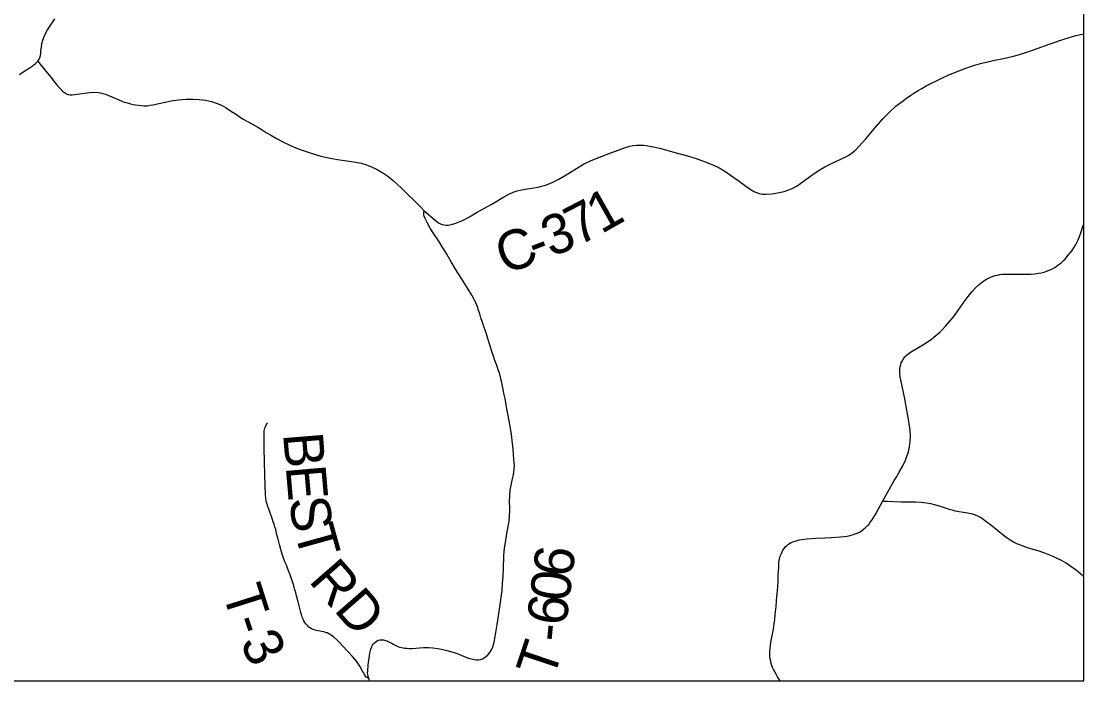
# Model space of a CAD drawing. Extents: x -10.5 to 40.6, y -3.2 to 22.
# Drawn here: x -5.263 to -3.744, y 14.1 to 15.042 of the extents above; entities that cross this region are included whole.
import ezdxf

# ---------------------------------------------------------------- set-up
doc = ezdxf.new("R2010")
doc.units = 0
for name, color, linetype in [('GM_X_County_Road', 7, 'Continuous'), ('GM_X_County_Road_Text', 7, 'Continuous'), ('GM_X_Township_Road', 7, 'Continuous'), ('GM_X_Township_Road_Text', 7, 'Continuous'), ('GM_X_Township_Text', 7, 'Continuous')]:
    doc.layers.add(name, color=color, linetype=linetype)

msp = doc.modelspace()

# ---------------------------------------------------------------- linework, layer by layer
at = {"layer": 'GM_X_County_Road'}
for points in [[(-5.239, 14.9851), (-5.2371, 14.988), (-5.2358, 14.9913), (-5.2349, 14.9959), (-5.2345, 14.9996), (-5.2338, 15.0052), (-5.233, 15.0102), (-5.2317, 15.0151), (-5.2296, 15.021), (-5.228, 15.0244), (-5.225, 15.0299), (-5.2224, 15.0342), (-5.2196, 15.0383), (-5.2147, 15.0455)], [(-3.9978, 14.932), (-3.9914, 14.9365), (-3.9859, 14.9401), (-3.9809, 14.9432), (-3.9759, 14.9461), (-3.9695, 14.9497), (-3.9632, 14.953), (-3.9551, 14.957), (-3.9463, 14.9612), (-3.9382, 14.9649), (-3.9255, 14.9702), (-3.9116, 14.9756), (-3.9022, 14.9787), (-3.892, 14.9815), (-3.8739, 14.9857), (-3.8593, 14.9886), (-3.8468, 14.9915), (-3.8379, 14.9938), (-3.8243, 14.9982), (-3.811, 15.0031), (-3.7923, 15.0099), (-3.7717, 15.0168), (-3.7556, 15.0215), (-3.7445, 15.0242)], [(-5.2652, 14.966), (-5.2574, 14.9712), (-5.2526, 14.9742), (-5.2455, 14.9789), (-5.2418, 14.982), (-5.239, 14.9851)], [(-5.239, 14.9851), (-5.2374, 14.9833), (-5.234, 14.979), (-5.2307, 14.9749), (-5.2255, 14.9684), (-5.2224, 14.9646), (-5.2184, 14.9596), (-5.2168, 14.9571), (-5.2161, 14.9563)], [(-5.2161, 14.9563), (-5.2123, 14.9518), (-5.2076, 14.9462), (-5.2037, 14.9422), (-5.2009, 14.9401), (-5.1978, 14.9383), (-5.1962, 14.9376), (-5.1945, 14.9373), (-5.1927, 14.9371), (-5.1903, 14.9371), (-5.1861, 14.9373), (-5.1651, 14.9401), (-5.1582, 14.9405), (-5.1525, 14.9402), (-5.1475, 14.9393), (-5.1466, 14.939)], [(-5.1466, 14.939), (-5.1421, 14.9377), (-5.1334, 14.9342), (-5.1197, 14.9284), (-5.1154, 14.9265), (-5.1109, 14.9254), (-5.1065, 14.9242), (-5.1026, 14.9232), (-5.0993, 14.9226), (-5.0953, 14.922), (-5.0914, 14.9217), (-5.0871, 14.9214), (-5.0825, 14.9214), (-5.0784, 14.9219), (-5.0746, 14.9228), (-5.0484, 14.9282), (-5.0379, 14.9298), (-5.0273, 14.9307), (-5.0173, 14.9308), (-5.008, 14.9303), (-4.9993, 14.9291), (-4.9907, 14.9272), (-4.9829, 14.9247), (-4.9766, 14.922), (-4.9699, 14.9184), (-4.9622, 14.9133), (-4.9566, 14.9096), (-4.95, 14.9051), (-4.9464, 14.9028), (-4.9374, 14.8977), (-4.9248, 14.8906), (-4.9184, 14.8868), (-4.9125, 14.8832), (-4.9053, 14.8789), (-4.8981, 14.8746), (-4.8872, 14.8688), (-4.8737, 14.8626), (-4.8657, 14.8595), (-4.8486, 14.8537), (-4.8344, 14.8495), (-4.8212, 14.8462), (-4.8108, 14.8443), (-4.7974, 14.8424), (-4.7844, 14.8408), (-4.777, 14.8393), (-4.771, 14.8376), (-4.7622, 14.8342), (-4.7543, 14.8304), (-4.7461, 14.8257), (-4.7389, 14.8208), (-4.7312, 14.8145), (-4.7192, 14.8036), (-4.6922, 14.777), (-4.6871, 14.7713)], [(-4.1289, 14.8252), (-4.1226, 14.8294), (-4.1145, 14.8341), (-4.1057, 14.8384), (-4.0906, 14.8453), (-4.0836, 14.8489), (-4.0801, 14.8509), (-4.075, 14.8543), (-4.0701, 14.8584), (-4.0658, 14.8629), (-4.0559, 14.874), (-4.0415, 14.891), (-4.031, 14.9033), (-4.0218, 14.9127), (-4.0124, 14.921), (-4.0041, 14.9275), (-3.9978, 14.932)], [(-4.6871, 14.7713), (-4.6772, 14.7631), (-4.6713, 14.7578), (-4.6684, 14.7555), (-4.6654, 14.7537), (-4.6625, 14.7522), (-4.6586, 14.7511), (-4.6559, 14.7506), (-4.6528, 14.7508), (-4.648, 14.7516), (-4.6416, 14.7537), (-4.6314, 14.7581), (-4.6221, 14.7627), (-4.611, 14.7691), (-4.6008, 14.7751), (-4.5913, 14.7804), (-4.5833, 14.7851), (-4.5777, 14.7885), (-4.5722, 14.7917), (-4.5667, 14.7947), (-4.5599, 14.7978), (-4.5539, 14.7998), (-4.5454, 14.8019), (-4.5239, 14.8052), (-4.5173, 14.8068), (-4.5137, 14.8078), (-4.5097, 14.8092), (-4.5029, 14.8121), (-4.4947, 14.8163), (-4.4841, 14.8226), (-4.4693, 14.8319), (-4.4591, 14.8378), (-4.4495, 14.8424), (-4.4363, 14.848), (-4.4189, 14.8545), (-4.4007, 14.861), (-4.3978, 14.862), (-4.3931, 14.8634), (-4.3888, 14.8644), (-4.3831, 14.8649), (-4.3789, 14.8652), (-4.3736, 14.8649), (-4.3674, 14.8641), (-4.3594, 14.8626), (-4.3509, 14.8606), (-4.3437, 14.8588), (-4.3288, 14.8547), (-4.3109, 14.8496), (-4.2983, 14.8459), (-4.2854, 14.8413), (-4.2744, 14.8369), (-4.2654, 14.8325), (-4.2573, 14.8278), (-4.249, 14.8223), (-4.237, 14.8134), (-4.2256, 14.8049), (-4.2189, 14.8006), (-4.2158, 14.7989), (-4.2123, 14.7973), (-4.2083, 14.796), (-4.2036, 14.7951), (-4.1982, 14.795), (-4.1896, 14.7957), (-4.1798, 14.7972), (-4.1727, 14.7989), (-4.1689, 14.8001), (-4.1657, 14.8012), (-4.16, 14.8035), (-4.1542, 14.8068), (-4.1486, 14.8106), (-4.1313, 14.8236), (-4.1289, 14.8252)], [(-4.0319, 14.3561), (-4.0295, 14.3604), (-4.0177, 14.3817), (-4.0153, 14.3862), (-4.0127, 14.3903), (-4.0083, 14.398), (-4.0032, 14.4069), (-4.0011, 14.4111), (-3.9994, 14.4147), (-3.998, 14.4179), (-3.9967, 14.4215), (-3.995, 14.4268), (-3.9935, 14.434), (-3.9925, 14.4419), (-3.9922, 14.4487), (-3.9927, 14.4573), (-3.9944, 14.4701), (-3.9971, 14.4867), (-4.0001, 14.5025), (-4.006, 14.53), (-4.0066, 14.5339), (-4.0072, 14.5387), (-4.0073, 14.5431), (-4.0072, 14.5457), (-4.0068, 14.5488), (-4.006, 14.5516), (-4.0053, 14.5541), (-4.0041, 14.5567), (-4.0022, 14.5599), (-4.0002, 14.5625), (-3.9982, 14.5646), (-3.9959, 14.5663), (-3.9939, 14.5677), (-3.9919, 14.5692), (-3.9838, 14.5741), (-3.9784, 14.5772), (-3.9653, 14.5855), (-3.9618, 14.5881), (-3.9585, 14.5907), (-3.9506, 14.5976), (-3.9464, 14.6015), (-3.9418, 14.6064), (-3.9357, 14.6134), (-3.9325, 14.6172), (-3.9289, 14.6221), (-3.9167, 14.6393), (-3.9097, 14.6489), (-3.9038, 14.6562), (-3.8983, 14.6622), (-3.8936, 14.6665), (-3.8887, 14.6703), (-3.8833, 14.6737), (-3.8777, 14.6764), (-3.8711, 14.6786), (-3.8677, 14.6794), (-3.8643, 14.6801), (-3.8607, 14.6805), (-3.8562, 14.6809), (-3.8412, 14.6809), (-3.825, 14.6807), (-3.8202, 14.6808), (-3.8146, 14.6813), (-3.8095, 14.682), (-3.8052, 14.6828), (-3.801, 14.6838), (-3.7977, 14.6849), (-3.7937, 14.6863), (-3.79, 14.688), (-3.7868, 14.6898), (-3.7841, 14.6916), (-3.7815, 14.6934), (-3.7786, 14.6956), (-3.7762, 14.6974), (-3.7736, 14.7001), (-3.7711, 14.7024), (-3.7689, 14.7049), (-3.7637, 14.711), (-3.7611, 14.7144), (-3.7585, 14.7185), (-3.7564, 14.7221), (-3.7544, 14.7261), (-3.7526, 14.7298), (-3.7505, 14.7345), (-3.748, 14.7414), (-3.7451, 14.7502), (-3.7445, 14.7521)], [(-4.1784, 14.1), (-4.1789, 14.1008), (-4.1819, 14.1055), (-4.1842, 14.1092), (-4.186, 14.1126), (-4.1877, 14.1159), (-4.189, 14.1189), (-4.1901, 14.1217), (-4.1909, 14.1246), (-4.1918, 14.1278), (-4.1925, 14.1312), (-4.1929, 14.1346), (-4.1932, 14.1386), (-4.1931, 14.1416), (-4.1927, 14.146), (-4.192, 14.151), (-4.1909, 14.1573), (-4.1879, 14.1736), (-4.1866, 14.1815), (-4.1859, 14.1876), (-4.1853, 14.1944), (-4.1842, 14.2062), (-4.1835, 14.2139), (-4.1829, 14.2204), (-4.1823, 14.2284), (-4.1817, 14.2346), (-4.1813, 14.2414), (-4.1809, 14.2513), (-4.1804, 14.2618), (-4.1802, 14.2685), (-4.1798, 14.2716), (-4.1791, 14.2743), (-4.1781, 14.2778), (-4.1764, 14.2818), (-4.1754, 14.2842), (-4.1743, 14.2865), (-4.1727, 14.2888), (-4.171, 14.2911), (-4.1693, 14.2928), (-4.1677, 14.2942), (-4.1651, 14.296), (-4.1626, 14.2974), (-4.16, 14.2986), (-4.157, 14.2996), (-4.1539, 14.3005), (-4.1512, 14.3011), (-4.1477, 14.3018), (-4.1396, 14.3028), (-4.1278, 14.3037), (-4.1143, 14.3043), (-4.1048, 14.3048), (-4.0919, 14.3055), (-4.0869, 14.306), (-4.0827, 14.3067), (-4.0767, 14.308), (-4.0737, 14.3088), (-4.0709, 14.3099), (-4.0681, 14.311), (-4.0651, 14.3124), (-4.0622, 14.3141), (-4.0592, 14.3163), (-4.0568, 14.3182), (-4.0539, 14.3211), (-4.0517, 14.3234), (-4.0495, 14.3263), (-4.0469, 14.3298), (-4.0418, 14.3382), (-4.0378, 14.3455), (-4.0319, 14.3561)]]:
    msp.add_lwpolyline(points, dxfattribs=at)
at = {"layer": 'GM_X_Township_Road'}
for points in [[(-4.7662, 14.1034), (-4.7664, 14.1042), (-4.767, 14.1066), (-4.7676, 14.109), (-4.7677, 14.1115), (-4.7676, 14.1139), (-4.7668, 14.1225), (-4.7651, 14.1354), (-4.7644, 14.1394), (-4.764, 14.1413), (-4.7635, 14.1431), (-4.763, 14.1453), (-4.7622, 14.1474), (-4.7616, 14.1489), (-4.7607, 14.1507), (-4.7594, 14.1525), (-4.7581, 14.1542), (-4.7557, 14.1561), (-4.7536, 14.1573), (-4.752, 14.1578), (-4.7501, 14.1584), (-4.7483, 14.1586), (-4.7465, 14.1585), (-4.7449, 14.1583), (-4.7435, 14.158), (-4.742, 14.1575), (-4.74, 14.1568), (-4.7384, 14.1561), (-4.7365, 14.1551), (-4.7328, 14.153), (-4.7302, 14.1516), (-4.7274, 14.1502), (-4.7246, 14.1491), (-4.722, 14.1481), (-4.7193, 14.1474), (-4.7168, 14.147), (-4.7145, 14.1465), (-4.7115, 14.1463), (-4.7079, 14.1459), (-4.7046, 14.1462), (-4.688, 14.1473), (-4.6806, 14.1474), (-4.6744, 14.1469), (-4.6676, 14.1459), (-4.6602, 14.1444), (-4.6544, 14.1431), (-4.6495, 14.1419), (-4.6443, 14.1404), (-4.6397, 14.1388), (-4.63, 14.1348), (-4.6237, 14.1324), (-4.6172, 14.1306), (-4.6124, 14.1298), (-4.6094, 14.1298), (-4.6063, 14.1303), (-4.6035, 14.1315), (-4.5998, 14.1338), (-4.5961, 14.137), (-4.5932, 14.1403), (-4.5909, 14.144), (-4.5888, 14.1485), (-4.5869, 14.1551), (-4.5853, 14.163), (-4.5828, 14.1802), (-4.5785, 14.2084), (-4.5765, 14.222), (-4.5756, 14.2291), (-4.5748, 14.2387), (-4.5739, 14.249), (-4.5738, 14.2597), (-4.5729, 14.2784), (-4.5724, 14.2851), (-4.5716, 14.292), (-4.5709, 14.2975), (-4.5699, 14.3036), (-4.5687, 14.3105), (-4.5673, 14.3177), (-4.5656, 14.3281), (-4.5648, 14.3361), (-4.5645, 14.3423), (-4.5644, 14.3482), (-4.5648, 14.3547), (-4.5646, 14.3652), (-4.5639, 14.372), (-4.5623, 14.3818), (-4.5609, 14.3885), (-4.5599, 14.3923), (-4.5589, 14.3975), (-4.5582, 14.4029), (-4.5579, 14.4072), (-4.5586, 14.416), (-4.5597, 14.4308), (-4.5622, 14.4518), (-4.5645, 14.4665), (-4.5682, 14.486), (-4.5714, 14.5025), (-4.5726, 14.5086), (-4.574, 14.5159), (-4.5764, 14.528), (-4.5772, 14.5314), (-4.5779, 14.5343), (-4.5787, 14.5372), (-4.5793, 14.5393), (-4.5807, 14.5429), (-4.5831, 14.5501), (-4.5858, 14.5573), (-4.5874, 14.5622), (-4.5902, 14.5703), (-4.5916, 14.5751), (-4.5927, 14.5786), (-4.5943, 14.584), (-4.5958, 14.5887), (-4.5985, 14.597), (-4.6012, 14.6046), (-4.6042, 14.6131), (-4.606, 14.6186), (-4.6076, 14.624), (-4.6091, 14.629), (-4.6104, 14.6331), (-4.6118, 14.6363), (-4.6133, 14.64), (-4.6152, 14.6436), (-4.619, 14.6507), (-4.624, 14.6593), (-4.6334, 14.6746), (-4.6421, 14.6881), (-4.6482, 14.6984), (-4.6541, 14.7082), (-4.6572, 14.714), (-4.661, 14.72), (-4.6661, 14.7279), (-4.6729, 14.7382), (-4.6782, 14.7465), (-4.682, 14.7536), (-4.6853, 14.7604), (-4.6867, 14.7635), (-4.6873, 14.7654), (-4.6876, 14.7674), (-4.6875, 14.7695), (-4.6871, 14.7713)], [(-4.7662, 14.1034), (-4.768, 14.1043), (-4.7692, 14.1051), (-4.7701, 14.1058), (-4.7711, 14.1071), (-4.7719, 14.1083), (-4.7729, 14.11), (-4.7737, 14.1118), (-4.7749, 14.1139), (-4.7788, 14.1209), (-4.7836, 14.1281), (-4.7892, 14.1348), (-4.7964, 14.1424), (-4.8031, 14.1495), (-4.8069, 14.1535), (-4.8088, 14.1555), (-4.8108, 14.1575), (-4.8163, 14.1625), (-4.8182, 14.1641), (-4.8208, 14.1657), (-4.823, 14.1671), (-4.8256, 14.1684), (-4.8278, 14.169), (-4.8305, 14.1697), (-4.8414, 14.1719), (-4.8437, 14.1726), (-4.846, 14.1734), (-4.8479, 14.1743), (-4.8498, 14.1755), (-4.8515, 14.1766), (-4.8532, 14.1782), (-4.8548, 14.18), (-4.856, 14.1815), (-4.8573, 14.1834), (-4.8587, 14.1855), (-4.8599, 14.1879), (-4.8611, 14.1907), (-4.8624, 14.1944), (-4.8631, 14.1973), (-4.8653, 14.2051), (-4.8671, 14.2129), (-4.8692, 14.2213), (-4.8705, 14.2259), (-4.872, 14.2314), (-4.8732, 14.2359), (-4.8749, 14.2414), (-4.8764, 14.2457), (-4.8783, 14.2514), (-4.8807, 14.2572), (-4.8825, 14.262), (-4.8838, 14.2653), (-4.8854, 14.269), (-4.8882, 14.2763), (-4.8898, 14.2806), (-4.8917, 14.2875), (-4.8937, 14.2945), (-4.8956, 14.302), (-4.8973, 14.3083), (-4.8991, 14.3158), (-4.9003, 14.3198), (-4.9015, 14.3237), (-4.9025, 14.3268), (-4.9038, 14.3302), (-4.9052, 14.3344), (-4.908, 14.3421), (-4.9091, 14.3453), (-4.9102, 14.3487), (-4.9113, 14.3523), (-4.912, 14.3547), (-4.9126, 14.3572), (-4.9132, 14.361), (-4.9135, 14.3655), (-4.9141, 14.3804), (-4.9145, 14.394), (-4.9151, 14.4133), (-4.9154, 14.4319), (-4.9155, 14.4456), (-4.9154, 14.4539), (-4.9154, 14.4571), (-4.915, 14.4589), (-4.9147, 14.4606), (-4.9141, 14.4623), (-4.9133, 14.464), (-4.9119, 14.4666), (-4.9107, 14.4689)], [(-3.7445, 14.2488), (-3.7454, 14.2496), (-3.7555, 14.2578), (-3.763, 14.2634), (-3.7697, 14.2679), (-3.7761, 14.2717), (-3.7833, 14.2753), (-3.7884, 14.2776), (-3.7976, 14.2812), (-3.807, 14.2845), (-3.8248, 14.29), (-3.8336, 14.293), (-3.84, 14.2956), (-3.845, 14.298), (-3.8498, 14.3008), (-3.854, 14.3035), (-3.8594, 14.3077), (-3.87, 14.3163), (-3.8797, 14.3241), (-3.8861, 14.3291), (-3.8912, 14.3325), (-3.8956, 14.335), (-3.899, 14.3364), (-3.9031, 14.3378), (-3.9079, 14.3389), (-3.9165, 14.3401), (-3.9227, 14.3411), (-3.9251, 14.3417), (-3.9281, 14.3424), (-3.9305, 14.343), (-3.9365, 14.3445), (-3.9477, 14.3484), (-3.956, 14.3509), (-3.9632, 14.3527), (-3.9694, 14.3537), (-3.9768, 14.3545), (-3.9842, 14.355), (-3.9966, 14.3551), (-4.0053, 14.3551), (-4.0159, 14.3554), (-4.0251, 14.3558), (-4.0319, 14.3561)], [(-4.7649, 14.1), (-4.7657, 14.102), (-4.7662, 14.1034)]]:
    msp.add_lwpolyline(points, dxfattribs=at)
at = {"layer": 'GM_X_Township_Text'}
msp.add_lwpolyline([(-6.1874, 16.891), (-6.1985, 16.7494), (-6.1956, 16.4198), (-6.1883, 16.2366), (-6.1993, 15.3843), (-6.2122, 14.1), (-3.7445, 14.1), (-3.7445, 16.8499)], dxfattribs=at)

# ---------------------------------------------------------------- texts
at = {"layer": 'GM_X_County_Road_Text'}
for s, rotation, p in [('7', 27.4691, (-4.4671, 14.7203)), ('1', 29.5196, (-4.4341, 14.7375)), ('3', 21.4703, (-4.5056, 14.7048)), ('C', 21.0092, (-4.5714, 14.6795)), ('-', 21.0715, (-4.5277, 14.6963))]:
    msp.add_text(s, height=0.0568, rotation=rotation, dxfattribs=at).set_placement(p)
at = {"layer": 'GM_X_Township_Road_Text'}
for s, height, rotation, p in [('B', 0.0568, 274.7319, (-4.8886, 14.4527)), ('E', 0.0568, 274.976, (-4.8848, 14.4059)), ('S', 0.0568, 279.031, (-4.8805, 14.3592)), ('T', 0.0568, 285.5435, (-4.873, 14.3145)), ('6', 0.0568, 82.9577, (-4.4755, 14.2467)), ('RD', 0.05682, 311.0922, (-4.8532, 14.2422)), ('0', 0.0568, 82.9438, (-4.4798, 14.212)), ('T', 0.0568, 287.5974, (-4.9758, 14.2269)), ('6', 0.0568, 82.8517, (-4.4842, 14.1772)), ('-', 0.0568, 288.0595, (-4.9628, 14.1859)), ('3', 0.0568, 298.0327, (-4.9513, 14.1538)), ('-', 0.0568, 84.5179, (-4.4864, 14.1544)), ('T', 0.0568, 71.5325, (-4.5027, 14.1003))]:
    msp.add_text(s, height=height, rotation=rotation, dxfattribs=at).set_placement(p)

doc.saveas('drawing.dxf')
